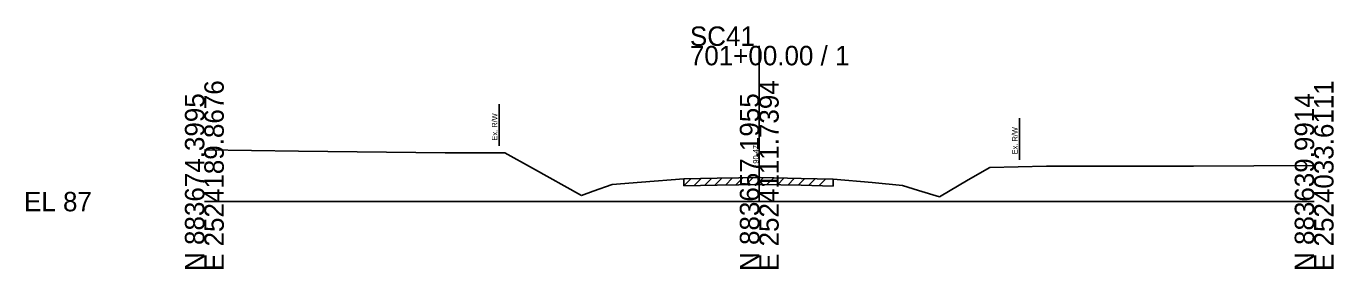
# Model space of a CAD drawing. Extents: x -26 to 183, y -10 to 24021.
# Drawn here: x -25.7 to 162.8, y 22490.3 to 22525.3 of the extents above; entities that cross this region are included whole.
import ezdxf

# ---------------------------------------------------------------- set-up
doc = ezdxf.new("R2010")
doc.units = 0
for name, color, linetype in [('RD_GPK_XS_Cell', 7, 'Continuous'), ('RD_XS_ExGround', 7, 'Continuous'), ('RD_XS_ExPaveRet', 7, 'Continuous'), ('RD_XS_ExRW', 7, 'Continuous'), ('RD_XS_TX_Elev_EX', 7, 'Continuous')]:
    doc.layers.add(name, color=color, linetype=linetype)

msp = doc.modelspace()

# ---------------------------------------------------------------- linework, layer by layer
at = {"layer": 'RD_GPK_XS_Cell'}
for p, q in [((80, 22500), (80, 22522.44)), ((0, 22500), (80, 22500)), ((80, 22500), (160, 22500))]:
    msp.add_line(p, q, dxfattribs=at)
at = {"layer": 'RD_XS_ExGround'}
for p, q in [((0, 22507.48), (13.58, 22507.29)), ((13.58, 22507.29), (34.72, 22507.02)), ((34.72, 22507.02), (43.34, 22507.02)), ((43.34, 22507.02), (47.29, 22504.82)), ((142.62, 22505.11), (160, 22505.19)), ((47.29, 22504.82), (54.37, 22500.89)), ((63.03, 22502.81), (69.11, 22503.28)), ((69.11, 22503.28), (73.94, 22503.37)), ((73.94, 22503.37), (80.2, 22503.47)), ((80.2, 22503.47), (86.06, 22503.35)), ((86.06, 22503.35), (90.65, 22503.24)), ((110.12, 22503.12), (113.23, 22504.92)), ((113.23, 22504.92), (121.39, 22505.11)), ((121.39, 22505.11), (142.62, 22505.11)), ((54.37, 22500.89), (56.05, 22501.48)), ((56.05, 22501.48), (58.81, 22502.44)), ((58.81, 22502.44), (63.03, 22502.81)), ((90.65, 22503.24), (96.28, 22502.73)), ((96.28, 22502.73), (100.63, 22502.32)), ((100.63, 22502.32), (102.95, 22501.61)), ((102.95, 22501.61), (105.98, 22500.7)), ((105.98, 22500.7), (110.12, 22503.12))]:
    msp.add_line(p, q, dxfattribs=at)
at = {"layer": 'RD_XS_ExPaveRet'}
for p, q in [((69.11, 22502.28), (70.12, 22503.3)), ((69.11, 22502.28), (69.11, 22503.28)), ((70.61, 22502.31), (71.62, 22503.33)), ((72.11, 22502.33), (73.12, 22503.35)), ((73.61, 22502.36), (74.62, 22503.38)), ((75.11, 22502.39), (76.12, 22503.4)), ((76.61, 22502.41), (77.62, 22503.43)), ((78.11, 22502.44), (79.12, 22503.45)), ((79.61, 22502.46), (80.61, 22503.46)), ((81.11, 22502.45), (82.08, 22503.43)), ((82.61, 22502.42), (83.58, 22503.4)), ((84.11, 22502.39), (85.08, 22503.37)), ((85.61, 22502.36), (86.58, 22503.34)), ((87.11, 22502.32), (88.08, 22503.3)), ((88.61, 22502.29), (89.58, 22503.27)), ((69.11, 22502.28), (73.94, 22502.37)), ((73.94, 22502.37), (80.2, 22502.47)), ((80.2, 22502.47), (86.06, 22502.35)), ((86.06, 22502.35), (90.65, 22502.24)), ((90.65, 22503.24), (90.65, 22502.24))]:
    msp.add_line(p, q, dxfattribs=at)
at = {"layer": 'RD_XS_ExRW'}
for p, q in [((42.5, 22514.02), (42.5, 22508.02)), ((117.5, 22512.02), (117.5, 22506.02))]:
    msp.add_line(p, q, dxfattribs=at)

# ---------------------------------------------------------------- texts
at = {"layer": 'RD_GPK_XS_Cell'}
for s, p in [('SC41', (70, 22522.44)), ('701+00.00 / 1', (70, 22519.64)), ('EL 87', (-26, 22498.6))]:
    msp.add_text(s, height=2.8, dxfattribs=at).set_placement(p)
for s, p in [('E 2524189.8676', (2.8, 22490)), ('E 2524111.7394', (82.8, 22490)), ('E 2524033.6111', (162.8, 22490)), ('N 883674.3995', (0, 22490)), ('N 883657.1955', (80, 22490)), ('N 883639.9914', (160, 22490))]:
    msp.add_text(s, height=2.8, rotation=90, dxfattribs=at).set_placement(p)
at = {"layer": 'RD_XS_ExRW'}
for p in [(42.25, 22508.8), (117.25, 22506.81)]:
    msp.add_text('Ex. R/W ', height=0.8, rotation=90, dxfattribs=at).set_placement(p)
at = {"layer": 'RD_XS_TX_Elev_EX'}
msp.add_text('90.47', height=0.8, rotation=90, dxfattribs=at).set_placement((79.9, 22505.47))

doc.saveas('drawing.dxf')
